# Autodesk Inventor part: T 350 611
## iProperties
Company: Mayer & Müller AG Schaltgeräte
Created: 2006-03
Part Number: T 350 611
Material: 2.0060.30
Document SubType Name: Modeling
Designer: I.Baliuc
Description: Stromschiene
Density: 8.94 g/cm^3
HalbzeugNorm: DIN 1759
Abmessung: Fl.Cu. 120x25-320
Author: T.Messerschmitt
Keywords: 382054
Revision Number: 350611
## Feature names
1. Extrusion2
2. Bohrung_Ø13.5 [Hole]
3. Bohrung_Ø18 [Hole]
